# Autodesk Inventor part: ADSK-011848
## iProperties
Shininess: 0.0
Length Units: 11272
Angle Units: 11279
Time Units: 11290
Mass Units: 11286
Length Display Precision: 3
Angle Display Precision: 2
Compacted: True
Created: 1999-08
Part Number: ADSK-011848
Document SubType Name: Modeling
Density: 0.0
Volumn: 0.0
Area: 0.0
PropertySet Name: Model Information
Control State: 0
Master: False
Checked Out: False
Revision Number: -
Title: ADSK-011848
